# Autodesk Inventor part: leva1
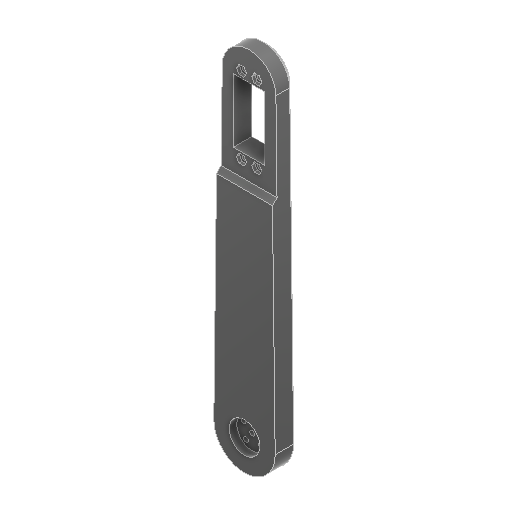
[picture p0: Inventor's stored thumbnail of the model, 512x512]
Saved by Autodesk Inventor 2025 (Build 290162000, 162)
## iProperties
Created: 2025-05
Part Number: leva1
Material: Plastica ABS
Document SubType Name: Modeling
Designer: R5800u
Density: 1.06 g/cm^3
Appearance: Liscia - Nero
Author: R5800u
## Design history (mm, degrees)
sketch "Schizzo1"
  geometry: L1 (-17.513, 200.217)-(-19.998, 0.249); L2 (17.484, 200.22)-(19.998, 0.251); A1 r 20 centre (0, 0) between (-19.998, 0.249) and (19.998, 0.251); A2 r 17.5 centre (-0.015, 200) between (-17.513, 200.217) and (17.484, 200.22); 1 further point
  constraints: 4 end point, 4 point on circle, 4 tangent, 2 centre point, 1 coincident
  dimensions: "d0" = 40 diameter of A1; "d1" = 35 diameter of A2; "d2" = 200 distance of point (0, 0) A2.centre
extrude "Estrusione1" new body sketch "Schizzo1" distance "d3" = 15; taper "d4" = 0 deg
sketch "Schizzo2"
  geometry: C1 r 10 at (0, 0); 1 further point
  constraints: 1 centre point, 1 coincident
  dimensions: "d5" = 20 diameter of C1
extrude "Estrusione2" cut sketch "Schizzo2" distance "d6" = 5; taper "d7" = 0 deg
sketch "Schizzo3"
  geometry: C1 r 10 at (0, 0) reference; 2 further points
  constraints: 1 coincident
hole "Foro1" sketch "Schizzo3" at (0, 0) diameter "d8" = 3.2; stored, may be unused: countersink angle "d12" = 90 deg, drill point angle "d14" = 118 deg; dims "d9" = 6, "d10" = 6.3, "d11" = 2, "d13" = 20
sketch "Schizzo6"
  geometry: C1 r 11 at (-0.001, 190); A1 r 17.5 centre (-0.015, 200) between (17.484, 200.22) and (-17.513, 200.217) reference; 1 further point
  constraints: 1 centre point
  dimensions: "d27" = 22 diameter of C1; "d44" = 10 distance of C1.centre A1.centre
extrude "Estrusione4" cut sketch "Schizzo6" distance "d28" = 5; taper "d29" = 0 deg
sketch "Schizzo7"
  geometry: L1 (-17.513, 200.217)-(-19.998, 0.249) reference; L2 (19.998, 0.251)-(17.484, 200.22) reference; L3 (-18.262, 140)-(18.241, 140); C1 r 11 at (-0.001, 190) reference; C2 r 10 at (0, 0) reference; A1 r 17.5 centre (-0.015, 200) between (17.484, 200.22) and (-17.513, 200.217) reference; A2 r 20 centre (0, 0) between (-19.998, 0.249) and (19.998, 0.251) reference; 1 further point
  constraints: 2 end point, 2 point on line, 1 horizontal
  dimensions: "d33" = 60 distance from line of A1.centre L3
extrude "Estrusione5" cut sketch "Schizzo7" distance "d31" = 3; taper "d32" = 0 deg
chamfer "Smusso1" distance "d34" = 3; stored, may be unused: second distance "d35" = 2, angle "d36" = 45 deg
sketch "Schizzo8"
  geometry: C1 r 1.6 at (0, 0) reference; 2 further points
  constraints: 1 coincident
hole "Foro3" sketch "Schizzo8" at (0, 0) diameter "d37" = 3.2; stored, may be unused: countersink angle "d41" = 90 deg, drill point angle "d43" = 118 deg; dims "d38" = 6, "d39" = 7, "d40" = 3, "d42" = 8
sketch "Schizzo9"
  geometry: C1 r 11 at (0, 0) reference; 2 further points
  constraints: 1 coincident
hole "Foro4" sketch "Schizzo9" at (0, 0) diameter "d45" = 3.2; stored, may be unused: countersink angle "d49" = 90 deg, drill point angle "d51" = 118 deg; dims "d46" = 6, "d47" = 7, "d48" = 3, "d50" = 8
sketch "Schizzo10"
  geometry: C1 r 1.25 at (5.717, 4.039) reference; C2 r 1.25 at (-4.039, 5.717) reference; C3 r 1.25 at (-5.717, -4.039) reference; C4 r 1.25 at (4.039, -5.717) reference; 1 further point
hole "Foro5" sketch "Schizzo10" at (5.717, 4.039), (4.039, -5.717), (-5.717, -4.039), (-4.039, 5.717) diameter "d52" = 3.2; stored, may be unused: countersink angle "d56" = 90 deg, drill point angle "d58" = 118 deg; dims "d53" = 6, "d54" = 11, "d55" = 2.6, "d57" = 8
chamfer "Smusso2" distance "d59" = 3; stored, may be unused: second distance "d60" = 2, angle "d61" = 45 deg
sketch "Schizzo11"
  geometry: L1 (-10.25, 198.8)-(-10.25, 157.3); L2 (-10.25, 157.3)-(10.25, 157.3); L3 (10.25, 157.3)-(10.25, 198.8); L4 (10.25, 198.8)-(-10.25, 198.8); L5 (-10.05, 196.1)-(-10.05, 160) reference; L6 (-8.05, 157.5)-(8.05, 157.5) reference; L7 (10.05, 160)-(10.05, 196.1) reference; L8 (-10.05, 196.1)-(-10.05, 160) reference; L9 (8.05, 198.6)-(-8.05, 198.6) reference; 1 further point
  constraints: 8 end point, 2 parallel, 2 perpendicular, 1 vertical
  dimensions: "d64" = 0.2 distance between parallel lines of L7 L3; "d65" = 0.2 distance between parallel lines of L6 L2; "d66" = 0.2 distance between parallel lines of L9 L4; "d67" = 0.2 distance between parallel lines of L5 L1
extrude "Estrusione6" cut sketch "Schizzo11" extent not by distance; stored distance "d62" = 5; taper "d63" = 0 deg
sketch "Schizzo12"
  geometry: A1 r 2.075 centre (5, 153) between (6, 151.182) and (4, 151.182) reference; A2 r 2.075 centre (-5, 153) between (-4, 151.182) and (-6, 151.182) reference; A3 r 2.075 centre (5, 203.1) between (4, 204.918) and (6, 204.918) reference; A4 r 2.075 centre (-5, 203.1) between (-6, 204.918) and (-4, 204.918) reference; 1 further point
hole "Foro6" sketch "Schizzo12" at (-5, 153), (5, 153), (-5, 203.1), (5, 203.1) diameter "d68" = 3.2; stored, may be unused: countersink angle "d72" = 90 deg, drill point angle "d74" = 118 deg; dims "d69" = 6, "d70" = 11, "d71" = 2.6, "d73" = 8
sketch "Schizzo13"
  geometry: L1 (-6.601, 198.8)-(6.599, 198.8) reference; L2 (-10.25, 186.004)-(-10.25, 193.996) reference; L3 (10.25, 193.988)-(10.25, 186.012) reference; A1 r 11 centre (-0.001, 190) between (6.599, 198.8) and (-6.601, 198.8) reference; A2 r 11 centre (-0.001, 190) between (-10.25, 193.996) and (-10.25, 186.004) reference; A3 r 11 centre (-0.001, 190) between (10.25, 186.012) and (10.25, 193.988) reference; 1 further point
extrude "Estrusione7" join sketch "Schizzo13" stored distance "d75" = 10; taper "d76" = 0 deg
sketch "Schizzo14"
  geometry: L1 (-5, 150.25)-(-6.588, 150.25) reference; L2 (-6.588, 155.75)-(-5, 155.75) reference; L3 (-8.291, 153)-(-6.645, 155.85); L4 (-6.645, 155.85)-(-3.355, 155.85); L5 (-3.355, 155.85)-(-1.709, 153); L6 (-1.709, 153)-(-3.355, 150.15); L7 (-3.355, 150.15)-(-6.645, 150.15); L8 (-6.645, 150.15)-(-8.291, 153); L9 (1.709, 153)-(3.355, 155.85); L10 (3.355, 155.85)-(6.645, 155.85); L11 (6.645, 155.85)-(8.291, 153); L12 (8.291, 153)-(6.645, 150.15); L13 (6.645, 150.15)-(3.355, 150.15); L14 (3.355, 150.15)-(1.709, 153); L15 (-8.291, 203.1)-(-6.645, 205.95); L16 (-6.645, 205.95)-(-3.355, 205.95); L17 (-3.355, 205.95)-(-1.709, 203.1); L18 (-1.709, 203.1)-(-3.355, 200.25); L19 (-3.355, 200.25)-(-6.645, 200.25); L20 (-6.645, 200.25)-(-8.291, 203.1); L21 (1.709, 203.1)-(3.355, 205.95); L22 (3.355, 205.95)-(6.645, 205.95); L23 (6.645, 205.95)-(8.291, 203.1); L24 (8.291, 203.1)-(6.645, 200.25); L25 (6.645, 200.25)-(3.355, 200.25); L26 (3.355, 200.25)-(1.709, 203.1); C1 r 1.6 at (-5, 153) reference; C2 r 1.6 at (5, 153) reference; C3 r 1.6 at (-5, 203.1) reference; C4 r 1.6 at (5, 203.1) reference; 9 further points
  constraints: 48 end point, 8 coincident, 52 other
  dimensions: "d84" = 5.7 distance between parallel lines of L10 L13; "d85" = 5.7 distance between parallel lines of L4 L7; "d86" = 5.7 distance between parallel lines of L19 L16; "d87" = 5.7 distance between parallel lines of L22 L25
extrude "Estrusione8" cut sketch "Schizzo14" distance "d88" = 2; taper "d89" = 0 deg
node "Solido1"
node "Linea chiusa proiettata1"
node "Riferimento2"
node "Riferimento3"
node "Riferimento4"
node "Riferimento5"
node "Riferimento6"
node "Riferimento7"
node "Riferimento8"
node "Riferimento9"
node "Riferimento10"
node "Riferimento11"
node "Riferimento12"
node "Riferimento13"
node "Riferimento14"
node "Linea chiusa proiettata2"
node "Linea chiusa proiettata3"
node "Linea chiusa proiettata4"
node "Riferimento15"
node "Riferimento16"
